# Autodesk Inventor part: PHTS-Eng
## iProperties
Shininess: 48.0
Length Units: 11272
Angle Units: 11279
Time Units: 11290
Mass Units: 11286
Length Display Precision: 5
Angle Display Precision: 2
Created: 2001-02
Part Number: PHTS-Eng
Material: Steel, Mild
Document SubType Name: Modeling
Designer: Administrator
Density: 7.86
Volumn: 0.4698874259452923
Area: 5.082331744338173
PropertySet Name: Model Information
Control State: 0
Master: False
Checked Out: False
Author: r cook
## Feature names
1. Body [Extrusion]
2. Head [Extrusion]
3. Knurl [Extrusion]
4. Chamfer1
5. Circular Pattern1
